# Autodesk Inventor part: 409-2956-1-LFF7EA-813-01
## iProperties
Created: 2010-11
Part Number: 409-2956-1-LFF7EA-813-01
Material: 3/8" OD TUBE - SS
Description: PT TUBING
Document SubType Name: Modeling
Designer: S. Boerckel
Engineer: Steve Boerckel
Mass: 769.029 g
Surface Area: 1665.99 cm^2
Volume: 95.1769 cm^3
Density: 8.08 g/cm^3
Length: 141.269 in
Author: S. Boerckel
Revision Number: 0
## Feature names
1. Sweep1
